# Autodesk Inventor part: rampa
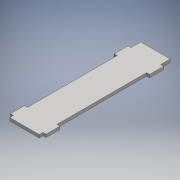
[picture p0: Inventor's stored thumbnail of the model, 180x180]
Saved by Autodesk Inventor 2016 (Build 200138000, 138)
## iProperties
Created: 2016-06
Part Number: rampa
Material: Genérico
Document SubType Name: Modeling
Designer: adm
Density: 1 g/cm^3
Appearance: Valor por defecto
Author: adm
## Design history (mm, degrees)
sketch "Boceto1"
  geometry: L1 (29.5, -125)-(-29.5, -125); L2 (-29.5, 125)-(29.5, 125); L3 (29.5, -125)-(-29.5, 125); L4 (-29.5, -125)-(29.5, 125); L5 (29.5, 117.561)-(35.5, 117.561); L6 (35.5, 117.561)-(35.5, 89.561); L7 (35.5, 89.561)-(29.5, 89.561); L8 (0, 0)-(-55.304, 0); L9 (0, 0)-(0, -42.823); L10 (-29.5, 117.561)-(-35.5, 117.561); L11 (-35.5, 117.561)-(-35.5, 89.561); L12 (-35.5, 89.561)-(-29.5, 89.561); L13 (35.5, -89.56)-(29.5, -89.56); L14 (35.5, -117.56)-(35.5, -89.56); L15 (29.5, -117.56)-(35.5, -117.56); L16 (-35.5, -89.561)-(-29.5, -89.561); L17 (-29.5, -117.561)-(-35.5, -117.561); L18 (-35.5, -117.561)-(-35.5, -89.561); L19 (29.5, -117.56)-(29.5, -125); L20 (-29.5, -125)-(-29.5, -117.561); L21 (-29.5, -89.561)-(-29.5, 89.561); L22 (-29.5, 117.561)-(-29.5, 125); L23 (29.5, 125)-(29.5, 117.561); L24 (29.5, 89.561)-(29.5, -89.56)
  constraints: 48 end point, 12 symmetric about line, 11 parallel, 4 perpendicular, 3 horizontal, 2 midpoint, 1 vertical
  dimensions: "d0" = 59 distance of L1.start L1.end; "d1" = 250 distance of L2.end L1.start; "d2" = 28 distance of L5.end L6.end; "d3" = 6 distance of L6.end L7.end; "d4" = 117.5605 distance from line of L5 L8.start
extrude "Extrusión1" new body sketch "Boceto1" distance "d5" = 6; taper "d6" = 0 deg
sketch "Boceto2"
  geometry: L1 (29.5, 125)-(-29.5, 125) reference; L2 (-29.5, 125)-(29.5, 125); L3 (29.5, 125)-(29.5, 137); L4 (29.5, 137)-(-29.5, 137); L5 (-29.5, 137)-(-29.5, 125); 1 further point
  constraints: 8 end point, 2 parallel, 1 horizontal, 1 perpendicular
  dimensions: "d7" = 12 distance of L3.end L2.end
extrude "Extrusión2" join sketch "Boceto2" distance "d8" = 6; taper "d9" = 0 deg
node "Sólido1"
